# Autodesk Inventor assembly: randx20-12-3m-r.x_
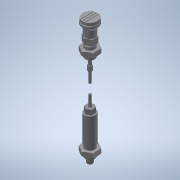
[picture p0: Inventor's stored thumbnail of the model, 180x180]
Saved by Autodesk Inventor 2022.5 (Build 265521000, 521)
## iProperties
Created: 2021-02
Part Number: randx20-12-3m-r.x_
Material: 一般
Document SubType Name: Assembly
Designer: ImaoCorp
Sending System: SOLIDWORKS 2019-2019304
MC: AMD64
MC_MODEL: Intel64 Family 6 Model 60 Stepping 3, GenuineIntel
OS: Windows_NT
FRU: Parasolid Version 31.0, build 290,  9- 1-2019
FORMAT: text
GUISE: transmit
KEY: randx20-12-3m-r
FILE: randx20-12-3m-r.x_t
DATE: Mon Feb 22 15:03:32 2021
Author: ImaoCorp
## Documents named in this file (5)
- X:\14_SW2022-Inv2022\00_全2023-1023新製品(TCC)まで\r\randx20-12-3m-r\RANDX20-12-3M-R.iam
- X:\14_SW2022-Inv2022\00_全2023-1023新製品(TCC)まで\r\randx20-12-3m-r\randx20-12-3m-r_01.ipt
- X:\14_SW2022-Inv2022\00_全2023-1023新製品(TCC)まで\r\randx20-12-3m-r\randx20-12-3m-r_02.ipt
- X:\14_SW2022-Inv2022\00_全2023-1023新製品(TCC)まで\r\randx20-12-3m-r\randx20-12-3m-r_03.ipt
- X:\14_SW2022-Inv2022\00_全2023-1023新製品(TCC)まで\r\randx20-12-3m-r\randx20-12-3m-r_04.ipt
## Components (4 placed, 4 different names)
1. randx20-12-3m-r_01
2. randx20-12-3m-r_02
3. randx20-12-3m-r_03
4. randx20-12-3m-r_04
